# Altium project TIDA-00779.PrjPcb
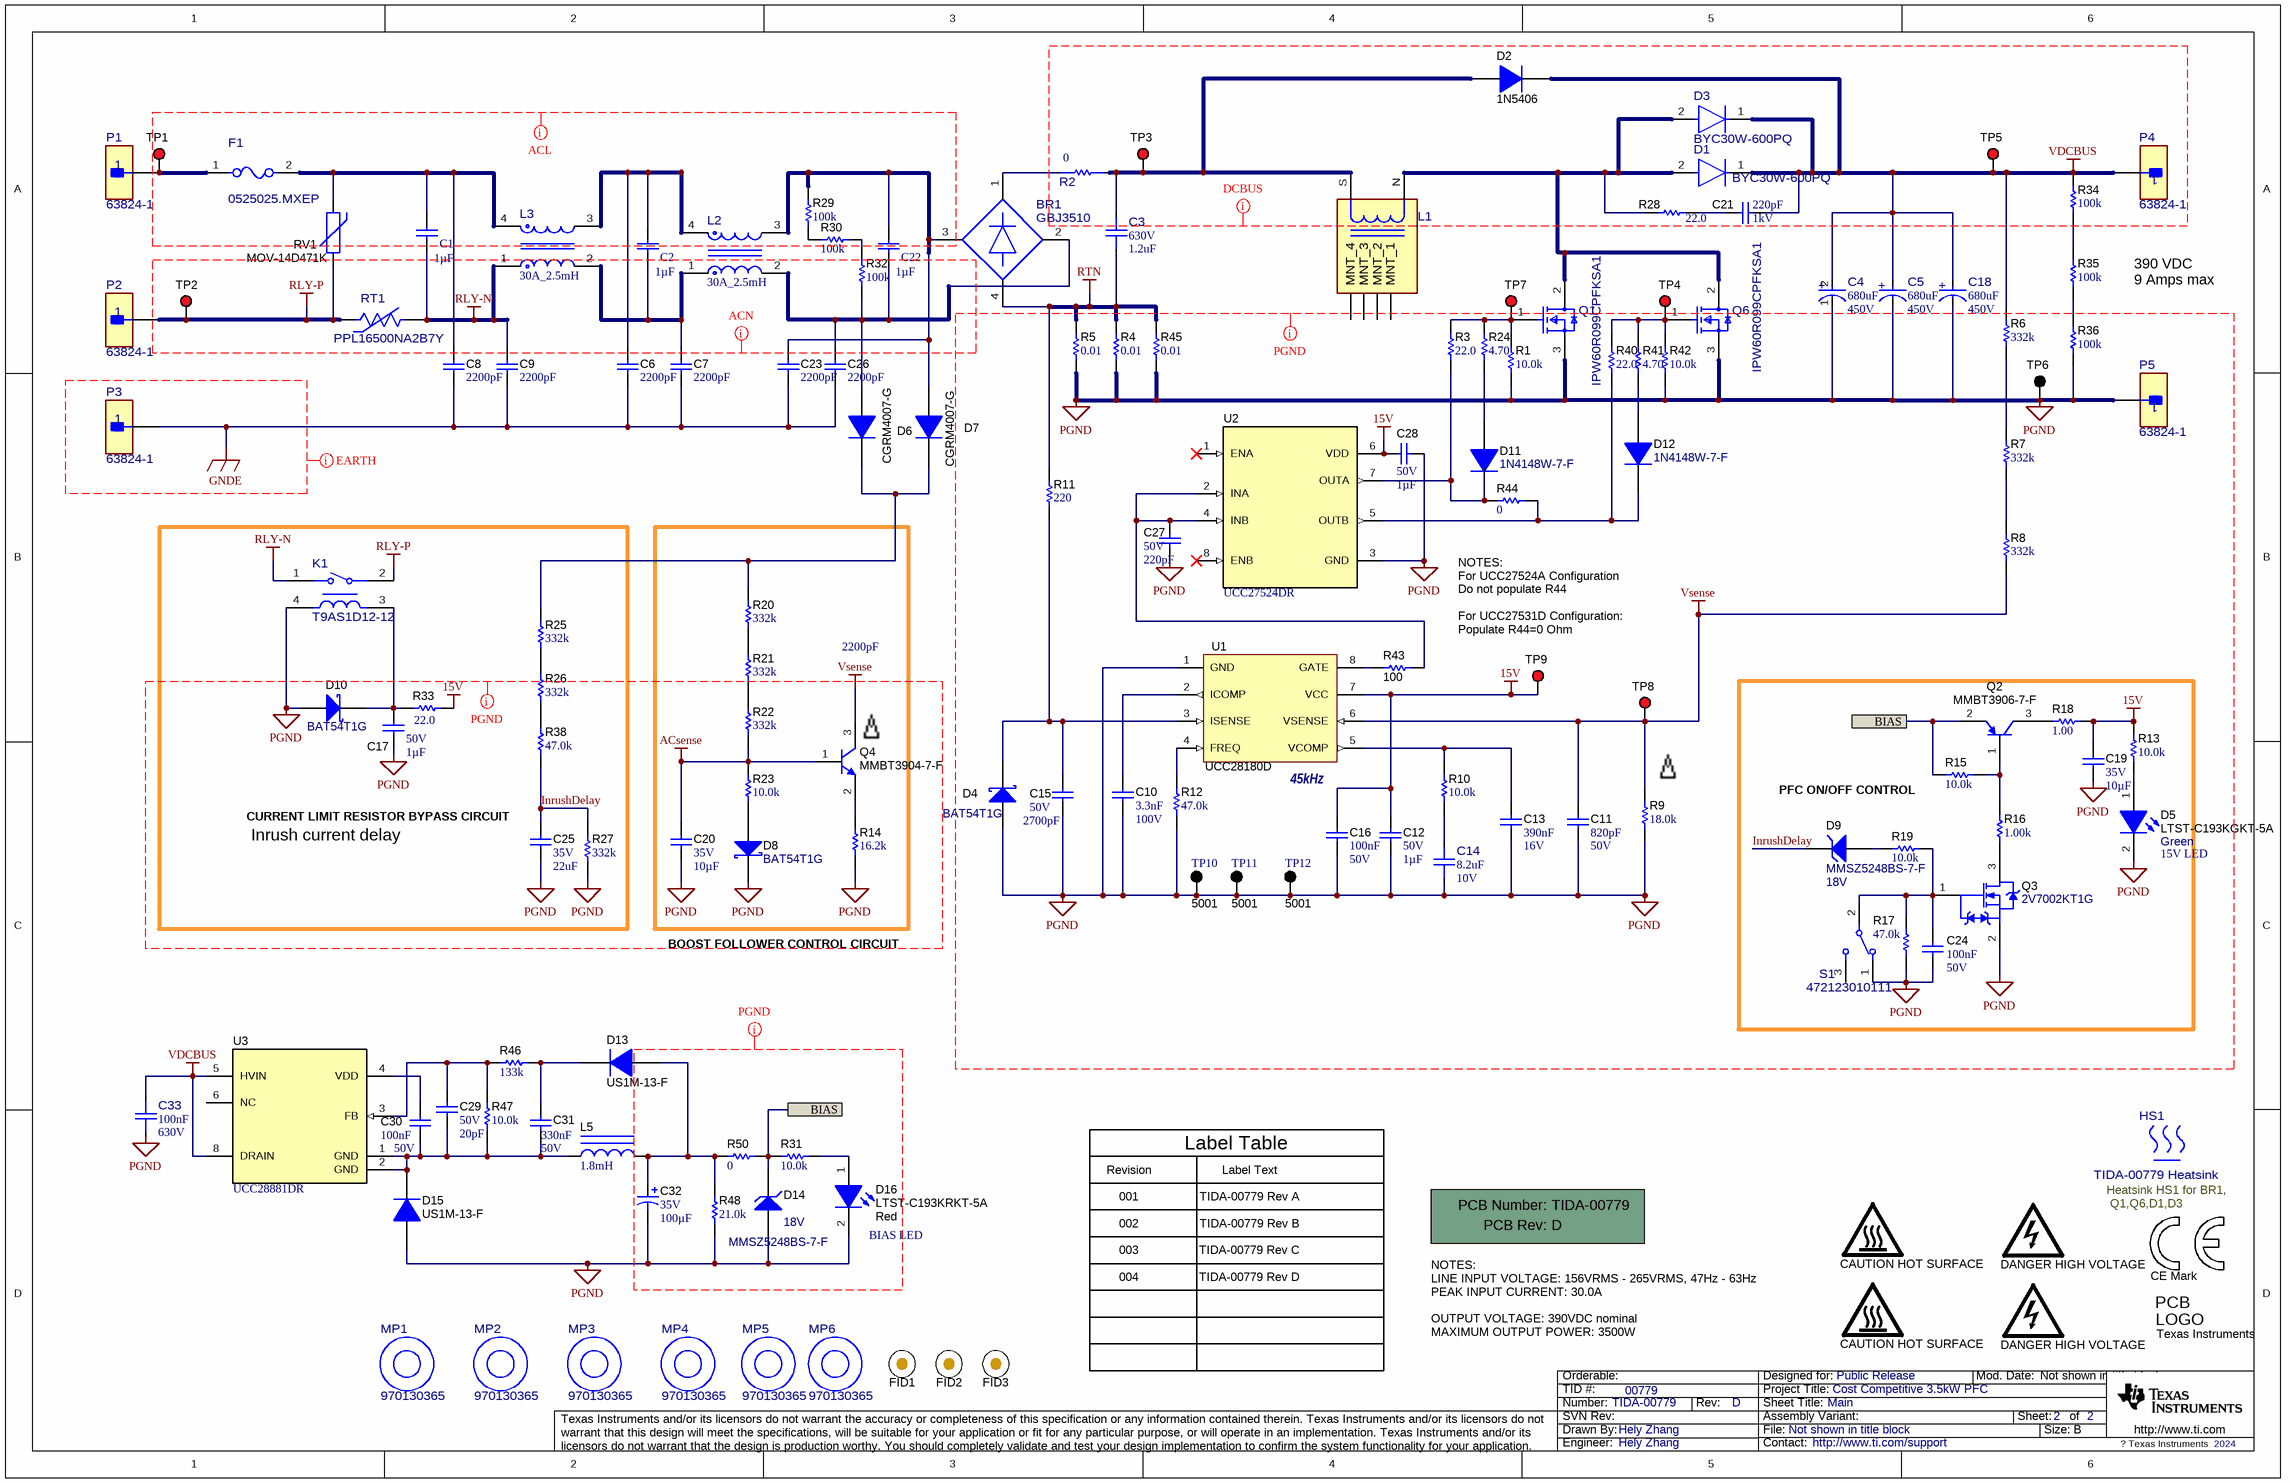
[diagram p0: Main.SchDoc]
CopyrightYear: 2024; PCB_Layout: Hely Zhang; PCB_Rev: D; PRJ_Customer: Public Release; PRJ_Engineer: Hely Zhang; PRJ_Number: TIDA-00779; PRJ_Title: Cost Competitive 3.5kW PFC; SCH_Rev: D; TechSupport: http://www.ti.com/support; TID: 00779
2 sheets, 148 parts. Net scope: flat (ports and power ports of the same name join across sheets).
Board file: TIDA-00779.PcbDoc
Sheets:
  BlockDiagram.SchDoc
  Main.SchDoc

## Sheet BlockDiagram.SchDoc: BlockDiagram
size A4; Date: Not shown in title block; ApprovedBy: Not shown in title block; CheckedBy: Not shown in title block; Author: Not shown in title block; CompanyName: Not shown in title block; DrawnBy: Hely Zhang; Engineer: Not shown in title block; Organization: Not shown in title block; Address1: Not shown in title block; Address2: Not shown in title block; Address3: Not shown in title block; Address4: Not shown in title block; DocumentNumber: 1; Revision: Use project parameter SCH_Rev; SheetNumber: 1; SheetTotal: 2; PageSetup: Record=PageOptions¦CenterHorizontal=True¦CenterVertical=True¦PrintScale=0.93¦XCorrection=1.00¦YCorrection=1.00¦PrintKind=0¦BorderSize=5000000¦LeftOffset=0¦BottomOffset=0¦Orientation=2¦PaperLength=1000¦PaperWidth=1000¦Scale=100¦PaperSource=15¦PrintQuality=600¦MediaType=1¦DitherType=10¦PaperKind=Letter¦PrintScaleMode=1

## Sheet Main.SchDoc: Main
size 431 x 279 mm; Date: Not shown in title block; ApprovedBy: Hely Zhang; CheckedBy: Hely Zhang; Author: Hely Zhang; CompanyName: TI; DrawnBy: Hely Zhang; Engineer: Not shown in title block; Organization: Not shown in title block; Address1: Not shown in title block; Address2: Not shown in title block; Address3: Not shown in title block; Address4: Not shown in title block; DocumentNumber: 1; Revision: Use project parameter SCH_Rev; SheetNumber: 2; SheetTotal: 2; PageSetup: Record=PageOptions¦CenterHorizontal=True¦CenterVertical=True¦PrintScale=0.62¦XCorrection=1.00¦YCorrection=1.00¦PrintKind=0¦BorderSize=5000000¦LeftOffset=0¦BottomOffset=0¦Orientation=2¦PaperLength=1000¦PaperWidth=1000¦Scale=100¦PaperSource=15¦PrintQuality=600¦MediaType=1¦DitherType=10¦PaperKind=Letter¦PrintScaleMode=1

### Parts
!PCB1  Printed Circuit Board  (value not drawn)  (mechanical)
BR1  GBJ3510  [FP-GBJ3510_HOR_GBJ3510_HOR-MFG]
C1  Cap_F: 1µF  [WCAP-FTXX_L26W11H20_CS]  (hidden comment: 890334026027CS)
C2  Cap_F: 1µF  [WCAP-FTXX_L26W11H20_CS]  (hidden comment: 890334026027CS)
C3  VDC_V: 630V  ValueDisplayed: 1.2uF  [FP-890334027012CS_RADIAL-MFG]  (hidden comment: 890334027012CS)
C4  ValueDisplayed: 680uF  VDC_V: 450V  [FP-861141486026_RADIAL-MFG]  (hidden comment: 861141486026)
C5  ValueDisplayed: 680uF  VDC_V: 450V  [FP-861141486026_RADIAL-MFG]  (hidden comment: 861141486026)
C6  ValueDisplayed: 2200pF  [KY_800x500x1100]  (hidden comment: DE2E3KY222MA2BM01F)
C7  ValueDisplayed: 2200pF  [KY_800x500x1100]  (hidden comment: DE2E3KY222MA2BM01F)
C8  ValueDisplayed: 2200pF  [KY_800x500x1100]  (hidden comment: DE2E3KY222MA2BM01F)
C9  ValueDisplayed: 2200pF  [KY_800x500x1100]  (hidden comment: DE2E3KY222MA2BM01F)
C10  Cap_F: 3.3nF  VDC_V: 100V  [0603]  (hidden comment: GRM188R72A332KA01D)
C11  Cap_F: 820pF  VDC_V: 50V  [0603]  (hidden comment: GRM188R71H821KA01D)
C12  VDC_V: 50V  ValueDisplayed: 1µF  [0603]  (hidden comment: GRT188R61H105ME13D)
C13  Cap_F: 390nF  VDC_V: 16V  [0603]  (hidden comment: GRM188R71C394KA88D)
C14  ValueDisplayed: 8.2uF  VDC_V: 10V  [FP-C1206C825M8RAC7800_1206-MFG]  (hidden comment: C1206C825M8RAC7800)
C15  VDC_V: 50V  ValueDisplayed: 2700pF  [0603]  (hidden comment: GRM1885C1H272JA01D)
C16  Cap_F: 100nF  VDC_V: 50V  [0603]  (hidden comment: GCM188R71H104KA57D)
C17  VDC_V: 50V  ValueDisplayed: 1µF  [0603]  (hidden comment: GRT188R61H105ME13D)
C18  ValueDisplayed: 680uF  VDC_V: 450V  [FP-861141486026_RADIAL-MFG]  (hidden comment: 861141486026)
C19  VDC_V: 35V  ValueDisplayed: 10µF  [1206]  (hidden comment: GRM319R6YA106KA12D)
C20  VDC_V: 35V  ValueDisplayed: 10µF  [1206]  (hidden comment: GRM319R6YA106KA12D)
C21  VDC_V: 1kV  ValueDisplayed: 220pF  [1206]  (hidden comment: GRM31A7U3A221JW31D)
C22  Cap_F: 1µF  [WCAP-FTXX_L26W11H20_CS]  (hidden comment: 890334026027CS)
C23  ValueDisplayed: 2200pF  [KY_800x500x1100]  (hidden comment: DE2E3KY222MA2BM01F)
C24  Cap_F: 100nF  VDC_V: 50V  [0603]  (hidden comment: GCM188R71H104KA57D)
C25  VDC_V: 35V  ValueDisplayed: 22uF  [1206_180]  (hidden comment: C3216X5R1V226M160AC)
C26  ValueDisplayed: 2200pF  [KY_800x500x1100]  (hidden comment: DE2E3KY222MA2BM01F)
C27  VDC_V: 50V  ValueDisplayed: 220pF  [0603]  (hidden comment: GRM1885C1H221JA01D)
C28  VDC_V: 50V  ValueDisplayed: 1µF  [0603]  (hidden comment: GRT188R61H105ME13D)
C29  VDC_V: 50V  ValueDisplayed: 20pF  [0603]  (hidden comment: GRM1885C1H200JA01D)
C30  Cap_F: 100nF  VDC_V: 50V  [0603]  (hidden comment: GCM188R71H104KA57D)
C31  Cap_F: 330nF  VDC_V: 50V  [0805_HV]  (hidden comment: GRM219R71H334KA88D)
C32  VDC_V: 35V  ValueDisplayed: 100µF  [Rubycon_630x1100]  (hidden comment: 35ZLJ100M6.3X11)
C33  ValueDisplayed: 100nF  VDC_V: 630V  [FP-885342211006_1812-MFG]  (hidden comment: 885342211006)
D1  BYC30W-600PQ  [FP-BYC30W-600PQ_HOR_TO-247-2-MFG]
D2  1N5406  [DO-201AD]
D3  BYC30W-600PQ  [FP-BYC30W-600PQ_HOR_TO-247-2-MFG]
D4  BAT54T1G  [SOD-123]
D5  LTST-C193KGKT-5A  value Green  [LTST-C193_Green]
D6  CGRM4007-G  [MINI-SMA]
D7  CGRM4007-G  [MINI-SMA]
D8  BAT54T1G  [SOD-123]
D9  MMSZ5248BS-7-F  value 18V  [SOD-323]
D10  BAT54T1G  [SOD-123]
D11  1N4148W-7-F  [SOD-123]
D12  1N4148W-7-F  [SOD-123]
D13  US1M-13-F  [SMA]
D14  MMSZ5248BS-7-F  value 18V  [SOD-323]
D15  US1M-13-F  [SMA]
D16  LTST-C193KRKT-5A  value Red  [LTST-C193_Red]
F1  0525025.MXEP  [FP-0525025.MXEP_AXIAL-MFG]
FID1  Fiducial  [Fiducial10-20]  (value not drawn)
FID2  Fiducial  [Fiducial10-20]  (value not drawn)
FID3  Fiducial  [Fiducial10-20]  (value not drawn)
HS1  TIDA-00779 Heatsink  [0-MFG]
K1  T9AS1D12-12  [FP-T9AS1D12-12_PTH_RELAY_27MM43_32MM51-MFG]
L1  30A_170uH  [FP-30A_170uH_PTH_IND_60MM0_51MM0-MFG]  (value not drawn)
L2  30A_2.5mH  [FP-30A_2.5mH_PTH_CMC_56MM0_42MM0-MFG]
L3  30A_2.5mH  [FP-30A_2.5mH_PTH_CMC_56MM0_42MM0-MFG]
L5  ValueDisplayed: 1.8mH  [WE-TI_8095]  (hidden comment: 768772182)
LOGO1  CAUTION HOT SURFACE  [IEC_HotSurface_Small]  (no BOM)
LOGO3  CAUTION HOT SURFACE  [IEC_HotSurface_Small]  (no BOM)
LOGO4  DANGER HIGH VOLTAGE  [IEC_HighVoltage_Small]  (no BOM)
Logo5  CE Mark  [CE_Mark_5mm]  (no BOM)
Logo6  Texas Instruments  [TI_Stacked_Overlay_Small]  (no BOM)
MP1  970130365  [FP-970130365_SPCAER_M3-MFG]
MP2  970130365  [FP-970130365_SPCAER_M3-MFG]
MP3  970130365  [FP-970130365_SPCAER_M3-MFG]
MP4  970130365  [FP-970130365_SPCAER_M3-MFG]
MP5  970130365  [FP-970130365_SPCAER_M3-MFG]
MP6  970130365  [FP-970130365_SPCAER_M3-MFG]
P1  63824-1  [FP-63824-1_CONN_7MM92_3MM11-MFG]
P2  63824-1  [FP-63824-1_CONN_7MM92_3MM11-MFG]
P3  63824-1  [FP-63824-1_CONN_7MM92_3MM11-MFG]
P4  63824-1  [FP-63824-1_CONN_7MM92_3MM11-MFG]
P5  63824-1  [FP-63824-1_CONN_7MM92_3MM11-MFG]
Q1  IPW60R099CPFKSA1  [FP-IPW60R099CPFKSA1_HOR_TO247-MFG]
Q2  MMBT3906-7-F  [SOT-23]
Q3  2V7002KT1G  [SOT-23]
Q4  MMBT3904-7-F  [SOT-23]
Q6  IPW60R099CPFKSA1  [FP-IPW60R099CPFKSA1_HOR_TO247-MFG]
R1  ValueDisplayed: 10.0k  [0603]  (hidden comment: RC0603FR-0710KL)
R2  value 0  [FP-RC2512FK-070RL_2512-MFG]  (hidden comment: RC2512FK-070RL)
R3  ValueDisplayed: 22.0  [1206]  (hidden comment: RC1206FR-0722RL)
R4  ValueDisplayed: 0.01  [2512]  (hidden comment: ERJ-M1WSF10MU)
R5  ValueDisplayed: 0.01  [2512]  (hidden comment: ERJ-M1WSF10MU)
R6  ValueDisplayed: 332k  [1206]  (hidden comment: RC1206FR-07332KL)
R7  ValueDisplayed: 332k  [1206]  (hidden comment: RC1206FR-07332KL)
R8  ValueDisplayed: 332k  [1206]  (hidden comment: RC1206FR-07332KL)
R9  ValueDisplayed: 18.0k  [0603]  (hidden comment: RC0603FR-0718KL)
R10  ValueDisplayed: 10.0k  [0603]  (hidden comment: RC0603FR-0710KL)
R11  ValueDisplayed: 220  [0603]  (hidden comment: RC0603FR-07220RL)
R12  ValueDisplayed: 47.0k  [0603]  (hidden comment: RC0603FR-0747KL)
R13  ValueDisplayed: 10.0k  [0603]  (hidden comment: RC0603FR-0710KL)
R14  ValueDisplayed: 16.2k  [0603]  (hidden comment: RC0603FR-0716K2L)
R15  ValueDisplayed: 10.0k  [0603]  (hidden comment: RC0603FR-0710KL)
R16  ValueDisplayed: 1.00k  [0603]  (hidden comment: RC0603FR-071KL)
R17  ValueDisplayed: 47.0k  [0603]  (hidden comment: RC0603FR-0747KL)
R18  ValueDisplayed: 1.00  [1206]  (hidden comment: RC1206FR-071RL)
R19  ValueDisplayed: 10.0k  [0603]  (hidden comment: RC0603FR-0710KL)
R20  ValueDisplayed: 332k  [1206]  (hidden comment: RC1206FR-07332KL)
R21  ValueDisplayed: 332k  [1206]  (hidden comment: RC1206FR-07332KL)
R22  ValueDisplayed: 332k  [1206]  (hidden comment: RC1206FR-07332KL)
R23  ValueDisplayed: 10.0k  [0603]  (hidden comment: RC0603FR-0710KL)
R24  ValueDisplayed: 4.70  [1206]  (hidden comment: RC1206FR-074R7L)
R25  ValueDisplayed: 332k  [1206]  (hidden comment: RC1206FR-07332KL)
R26  ValueDisplayed: 332k  [1206]  (hidden comment: RC1206FR-07332KL)
R27  ValueDisplayed: 332k  [1206]  (hidden comment: RC1206FR-07332KL)
R28  ValueDisplayed: 22.0  [1206]  (hidden comment: RC1206FR-0722RL)
R29  ValueDisplayed: 100k  [1206]  (hidden comment: RC1206FR-07100KL)
R30  ValueDisplayed: 100k  [1206]  (hidden comment: RC1206FR-07100KL)
R31  ValueDisplayed: 10.0k  [0603]  (hidden comment: RC0603FR-0710KL)
R32  ValueDisplayed: 100k  [1206]  (hidden comment: RC1206FR-07100KL)
R33  ValueDisplayed: 22.0  [1206]  (hidden comment: RC1206FR-0722RL)
R34  ValueDisplayed: 100k  [1206]  (hidden comment: RC1206FR-07100KL)
R35  ValueDisplayed: 100k  [1206]  (hidden comment: RC1206FR-07100KL)
R36  ValueDisplayed: 100k  [1206]  (hidden comment: RC1206FR-07100KL)
R38  ValueDisplayed: 47.0k  [0603]  (hidden comment: RC0603FR-0747KL)
R40  ValueDisplayed: 22.0  [1206]  (hidden comment: RC1206FR-0722RL)
R41  ValueDisplayed: 4.70  [1206]  (hidden comment: RC1206FR-074R7L)
R42  ValueDisplayed: 10.0k  [0603]  (hidden comment: RC0603FR-0710KL)
R43  ValueDisplayed: 100  [0603]  (hidden comment: RT0603DRE07100RL)
R44  ValueDisplayed: 0  [0603]  (hidden comment: RC0603JR-070RL)
R45  ValueDisplayed: 0.01  [2512]  (hidden comment: ERJ-M1WSF10MU)
R46  ValueDisplayed: 133k  [0603]  (hidden comment: RC0603FR-07133KL)
R47  ValueDisplayed: 10.0k  [0603]  (hidden comment: RC0603FR-0710KL)
R48  ValueDisplayed: 21.0k  [0603]  (hidden comment: RC0603FR-0721KL)
R50  ValueDisplayed: 0  [0603]  (hidden comment: RC0603JR-070RL)
RT1  PPL16500NA2B7Y  [FP-PPL16500NA2B7Y_RADIAL-MFG]
RV1  MOV-14D471K  [Bourns_MOV-14D621K]
S1  472123010111  [FP-472123010111_PTH3-MFG]
TP1  5000  [Keystone5000]  (value not drawn)
TP2  5000  [Keystone5000]  (value not drawn)
TP3  5000  [Keystone5000]  (value not drawn)
TP4  5000  [Keystone5000]  (value not drawn)
TP5  5000  [Keystone5000]  (value not drawn)
TP6  5001  [Keystone5001]  (value not drawn)
TP7  5000  [Keystone5000]  (value not drawn)
TP8  5000  [Keystone5000]  (value not drawn)
TP9  5000  [Keystone5000]  (value not drawn)
TP10  5001  [Keystone5001]
TP11  5001  [Keystone5001]
TP12  5001  [Keystone5001]
U1  UCC28180D  [D0008A_N]
U2  UCC27524DR  [D0008A_N]
U3  UCC28881DR  [D0007A_N]
  DANGER HIGH VOLTAGE  [IEC_HighVoltage_Small]  (no BOM)

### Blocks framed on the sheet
Inrush current delay: C17 C25 D10 K1 R25-R27 R33 R38
2200pF: C20 D8 Q4 R14 R20-R23
15V LED: C19 C24 D5 D9 Q2 Q3 R13 R15-R19 S1

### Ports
BIAS

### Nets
15V: C12.1 C16.1 C19.1 C28.2 R13.1 R18.2 R33.1 TP9.1 U1.7(VCC) U2.6(VDD)
ACsense: C20.1 Q4.1(B) R22.1 R23.2
GNDE: C6.1 C7.1 C8.1 C9.1 C23.1 C26.1 P3.1
PGND: C4.1(CATHODE) C5.1(CATHODE) C10.2 C11.2 C12.2 C13.2 C14.1 C15.2 C16.2 C17.2 C18.1(CATHODE) C19.2 C20.2 C24.2 C25.2 C27.2 C28.1 C32.2(-) C33.1 D4.2(A) D5.2(K) D8.1(K) D10.2(A) D14.2(A) D15.2(A) D16.2(K) K1.4 P5.1 Q1.3(source) Q3.2(S) Q6.3(source) R1.1 R4.1 R5.1 R9.1 R12.1 R14.1 R17.1 R27.1 R36.1 R42.1 R45.1 R48.1 S1.1 TP6.1 TP10.1 TP11.1 TP12.1 U1.1(GND) U2.3(GND)
RLY-N: C1.1 C9.2 K1.1 L3.1 RT1.2
RLY-P: K1.2 P2.1 RT1.1 RV1.1 TP2.1
RTN: BR1.4(-) C3.1 R4.2 R5.2 R11.2 R45.2
VDCBUS: C4.2(ANODE) C5.2(ANODE) C18.2(ANODE) C21.1 C33.2 D1.1(K) D2.1(K) D3.1(K) P4.1 R6.2 R34.2 TP5.1 U3.5(HVIN) U3.8(DRAIN)
Vsense: C11.1 Q4.3(C) R8.1 R9.2 TP8.1 U1.6(VSENSE)
BIAS: D14.1(K) Q2.2(E) R15.1 R31.2 R50.2 ; port BIAS
InrushDelay: C25.1 D9.1(K) R27.2 R38.1
NetBR1_1: BR1.1(+) R2.1
NetBR1_2: BR1.2(1_~) C22.1 C26.2 D6.2(A) L2.2 R32.1
NetBR1_3: BR1.3(2_~) C22.2 C23.2 D7.2(A) L2.3 R29.2
NetC1_2: C1.2 C8.2 F1.2 L3.4 RV1.2
NetC2_1: C2.1 C7.2 L2.1 L3.2
NetC2_2: C2.2 C6.2 L2.4 L3.3
NetC3_2: C3.2 D2.2(A) L1.S R2.2 TP3.1
NetC10_1: C10.1 U1.2(ICOMP)
NetC13_1: C13.1 R10.2 U1.5(VCOMP)
NetC14_2: C14.2 R10.1
NetC15_1: C15.1 D4.1(K) R11.1 U1.3(ISENSE)
NetC17_1: C17.1 D10.1(K) K1.3 R33.2
NetC21_2: C21.2 R28.1
NetC24_1: C24.1 Q3.1(G) R17.2 R19.1 S1.2
NetC27_1: C27.1 R43.2 U2.2(INA) U2.4(INB)
NetC29_1: C29.1 R46.1 R47.2 U3.3(FB)
NetC29_2: C29.2 C30.2 C31.2 D15.1(K) L5.1 R47.1 U3.1(GND) U3.2(GND)
NetC30_1: C30.1 U3.4(VDD)
NetC31_1: C31.1 D13.1(K) R46.2
NetC32_1: C32.1(+) D13.2(A) L5.2 R48.2 R50.1
NetD1_2: D1.2(A) D3.2(A) L1.N Q1.2(drain) Q6.2(drain) R28.2
NetD5_1: D5.1(A) R13.2
NetD6_1: D6.1(K) D7.1(K) R20.2 R25.2
NetD8_2: D8.2(A) R23.1
NetD9_2: D9.2(A) R19.2
NetD11_1: D11.1(K) R3.1 R44.1 U2.7(OUTA)
NetD11_2: D11.2(A) R24.1
NetD12_1: D12.1(K) R40.1 R44.2 U2.5(OUTB)
NetD12_2: D12.2(A) R41.1
NetD16_1: D16.1(A) R31.1
NetF1_1: F1.1 P1.1 TP1.1
NetQ1_1: Q1.1(gate) R1.2 R3.2 R24.2 TP7.1
NetQ2_1: Q2.1(B) R15.2 R16.1
NetQ2_3: Q2.3(C) R18.1
NetQ3_3: Q3.3(D) R16.2
NetQ4_2: Q4.2(E) R14.2
NetQ6_1: Q6.1(gate) R40.2 R41.2 R42.2 TP4.1
NetR6_1: R6.1 R7.2
NetR7_1: R7.1 R8.2
NetR12_2: R12.2 U1.4(FREQ)
NetR20_1: R20.1 R21.2
NetR21_1: R21.1 R22.2
NetR25_1: R25.1 R26.2
NetR26_1: R26.1 R38.2
NetR29_1: R29.1 R30.2
NetR30_1: R30.1 R32.2
NetR34_1: R34.1 R35.2
NetR35_1: R35.1 R36.2
NetR43_1: R43.1 U1.8(GATE)

Not connected (* = marked no-connect by the designer): L1 1(MNT_1) 2(MNT_2) 3(MNT_3) 4(MNT_4); S1 3; U2 1(ENA)* 8(ENB)*; U3 6(NC)

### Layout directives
net class PGND: 15V, (no net found under the mark), ACsense, InrushDelay, PGND, Vsense
net class ACL: (no net found under the mark)
net class ACN: RLY-N, RLY-P
net class DCBUS: VDCBUS
net class EARTH: GNDE

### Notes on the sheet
- 390 VDC
  9 Amps max
- NOTES:
  For UCC27524A Configuration
  Do not populate R44
  For UCC27531D Configuration:
  Populate R44=0 Ohm
- CURRENT LIMIT RESISTOR BYPASS CIRCUIT
- (near U1) 45kHz
- (near R15) PFC ON/OFF CONTROL
- BOOST FOLLOWER CONTROL CIRCUIT
- Revision
- Label Table
- Label Text
- (near D16) BIAS LED
- 001
- 002
- TIDA-00779 Rev A
- TIDA-00779 Rev B
- Q1,Q6,D1,D3
- Heatsink HS1 for BR1,
- 003
- 004
- TIDA-00779 Rev C
- TIDA-00779 Rev D
- (near !PCB1) NOTES:
  LINE INPUT VOLTAGE: 156VRMS - 265VRMS, 47Hz - 63Hz
  PEAK INPUT CURRENT: 30.0A
  OUTPUT VOLTAGE: 390VDC nominal
  MAXIMUM OUTPUT POWER: 3500W

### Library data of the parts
!PCB1 = CMP-0003618-2: Manufacturer: Any; PartNumber: TIDA-00779
BR1 = CMP-0121868-2: Bridge Rectifier Single Phase Standard 1 kV Through Hole GBJ; Manufacturer: SMC Diode Solutions; PartNumber: GBJ3510_HOR; AEC Qualified: No; SizeZ_mm: 4.8mm; TJmax_C: 150°C; Vf_V: 1kV; Cap_F: 75pF; Forward Current: 35A; Max Surge Forward Current: 320A; Peak Reverse Current: 5uA; AEC Category: Q101; CompType: Diode
C1 C2 C22 = CMP-0112728-1: WCAP-FTXX Film Capacitor, THT, L26 x W11 x H20mm, 1µF, 310V; Manufacturer: Wurth Elektronik; Capacitance Tolerance: +/-10%; Dissipation Factor @10kHz: 0.7%; Dissipation Factor @1kHz: 0.1%; Insulation Resistance: 10000Ohm x F; Pitch: 22.5mm; Rate of Voltage Rise: 170V/us; Technical Reference: MXXP225105K310ACPP36004
C3 = CMP-0090546-1: 1.2µF Film Capacitor 310V  Polypropylene (PP), Metallized Radial; Manufacturer: Wurth Electronics; AEC Qualified: No; Tolerance_%: 10%; SizeZ_mm: 22.5mm
C4 C5 C18 = CMP-0035874-1: 680 µF 450 V Aluminum Electrolytic Capacitors Radial, Can - Snap-In 3000 Hrs @ 105°C; Manufacturer: Wurth Eectronics; AEC Qualified: No; Cap_F: 680µF; IRMS_A: 2.2A; SizeZ_mm: 59mm; Tolerance_%: 20%; Leakage Current: 1659.52uA; Life: 3000Hours; Value: 680µF
C6-C9 C23 C26 = CMP-0067532-1: CAP, CERM, 2200 pF, X1 250 VAC/Y2 250 VAC, +/- 20%, E, 8x5mm; Manufacturer: MuRata; TaMin_C: -40°C; AC_Safety: X1Y2; Polarized: N; SizeAreaWB_mm2: 70.0; Value1: Unknown; U/M: EA; Value: 2200pF; TaMax_C: 125°C; VAC_X: 250; SizeZ_mm: 11.0; SizeX_mm: 8.0; SizeY_mm: 5.0; Cap_Case: 8x5x11mm; Value2: V; SizeArea_mm2: 40.0; Cap_F: 2.2nF; AEC Category: Q200
C10 = CMP-0007479-4: CAP, CERM, 3300 pF, 100 V, +/- 10%, X7R, 0603; Manufacturer: MuRata; TaMin_C: -55°C; Polarized: N; SizeAreaWB_mm2: 4.68; Value1: Unknown; U/M: EA; Value: 3300pF; TaMax_C: 125°C; SizeZ_mm: 1; SizeX_mm: 1.6; SizeY_mm: 0.8; SizeArea_mm2: 1.28; AEC Category: Q200
C11 = CMP-0007464-4: CAP, CERM, 820 pF, 50 V, +/- 10%, X7R, 0603; Manufacturer: MuRata; TaMin_C: -55°C; Polarized: N; SizeAreaWB_mm2: 4.68; Value1: Unknown; U/M: EA; Value: 820pF; TaMax_C: 125°C; SizeZ_mm: 1; SizeX_mm: 1.6; SizeY_mm: 0.8; SizeArea_mm2: 1.28; AEC Category: Q200
C12 C17 C28 = CMP-0081784-1: CAP, CERM, 1 µF, 50 V,+/- 20%, X5R, AEC-Q200 Grade 3, 0603; Manufacturer: MuRata; TaMin_C: -55°C; Polarized: N; SizeAreaWB_mm2: 4.68; U/M: EA; Value: 1uF; TaMax_C: 85°C; SizeZ_mm: 1; SizeX_mm: 1.6; SizeY_mm: 0.8; SizeArea_mm2: 1.28; AEC Qualified: Y; AEC Grade: 3; AEC Category: Q200
C13 = CMP-0007395-4: CAP, CERM, 0.39 uF, 16 V, +/- 10%, X7R, 0603; Manufacturer: MuRata; TaMin_C: -55°C; Polarized: N; SizeAreaWB_mm2: 4.68; Value1: Unknown; U/M: EA; Value: 0.39uF; TaMax_C: 125°C; SizeZ_mm: 1; SizeX_mm: 1.6; SizeY_mm: 0.8; SizeArea_mm2: 1.28; AEC Category: Q200
C14 = CMP-0122046-1: Cap Ceramic 8.2uF 10V X7R 20% SMD 1206 125°C Plastic T/R; Manufacturer: KEMET; AEC Qualified: No; Cap_F: 8.2µF; SizeZ_mm: 1.8mm; TempCo: 15%; Value: 8.2µF
C15 = CMP-0007204-4: CAP, CERM, 2700 pF, 50 V, +/- 5%, C0G/NP0, 0603; Manufacturer: MuRata; TaMin_C: -55°C; Polarized: N; SizeAreaWB_mm2: 4.68; Value1: Unknown; U/M: EA; Value: 2700pF; TaMax_C: 125°C; SizeZ_mm: 1; SizeX_mm: 1.6; SizeY_mm: 0.8; SizeArea_mm2: 1.28; Cap_F: 2.7nF; AEC Category: Q200
C16 C24 C30 = CMP-0007144-4: CAP, CERM, 0.1 uF, 50 V, +/- 10%, X7R, 0603; Manufacturer: MuRata; TaMin_C: -55°C; ESR_ohm: 20m; Polarized: N; SizeAreaWB_mm2: 4.68; Value1: 0.02 ohm; U/M: EA; Value: 0.1uF; TaMax_C: 125°C; SizeZ_mm: 1; SizeX_mm: 1.6; SizeY_mm: 0.8; SizeArea_mm2: 1.28; IRMS_A: 1.84A; AEC Category: Q200
C19 C20 = CMP-0081637-1: CAP, CERM, 10 µF, 35 V,+/- 10%, X5R, 1206; Manufacturer: MuRata; TaMin_C: -55°C; ESR_ohm: 1m; Polarized: N; SizeAreaWB_mm2: 10.92; Value1: 0.001 ohm; U/M: EA; Value: 10uF; TaMax_C: 85°C; SizeZ_mm: 1.35; SizeX_mm: 3.2; SizeY_mm: 1.6; SizeArea_mm2: 5.12; IRMS_A: 6A; AEC Category: Q200
C21 = CMP-0008899-2: CAP, CERM, 220 pF, 1000 V, +/- 5%, U2J, 1206; Manufacturer: MuRata; TaMin_C: -55°C; Polarized: N; SizeAreaWB_mm2: 10.92; Value1: Unknown; U/M: EA; Value: 220pF; TaMax_C: 125°C; SizeZ_mm: 1.35; SizeX_mm: 3.2; SizeY_mm: 1.6; Value2: 1000V; SizeArea_mm2: 5.12; AEC Category: Q200
C25 = CMP-0008667-2: CAP, CERM, 22 uF, 35 V, +/- 20%, X5R, 1206; Manufacturer: TDK; TaMin_C: -55°C; ESR_ohm: 2.398m; Polarized: N; SizeAreaWB_mm2: 10.92; Value1: 0.002398 ohm; U/M: EA; Value: 22uF; TaMax_C: 85°C; SizeZ_mm: 1.8; SizeX_mm: 3.2; SizeY_mm: 1.6; SizeArea_mm2: 5.12; Cap_F: 22µF; IRMS_A: 4.6851A; AEC Category: Q200
C27 = CMP-0007197-4: CAP, CERM, 220 pF, 50 V, +/- 5%, C0G/NP0, 0603; Manufacturer: MuRata; TaMin_C: -55°C; Polarized: N; SizeAreaWB_mm2: 4.68; Value1: Unknown; U/M: EA; Value: 220pF; TaMax_C: 125°C; SizeZ_mm: 1; SizeX_mm: 1.6; SizeY_mm: 0.8; SizeArea_mm2: 1.28; AEC Category: Q200
C29 = CMP-0007193-4: CAP, CERM, 20 pF, 50 V, +/- 5%, C0G/NP0, 0603; Manufacturer: MuRata; TaMin_C: -55°C; Polarized: N; SizeAreaWB_mm2: 4.68; Value1: Unknown; U/M: EA; Value: 20pF; TaMax_C: 125°C; SizeZ_mm: 1; SizeX_mm: 1.6; SizeY_mm: 0.8; SizeArea_mm2: 1.28; AEC Category: Q200
C31 = CMP-0008227-2: CAP, CERM, 0.33 uF, 50 V, +/- 10%, X7R, 0805; Manufacturer: MuRata; TaMin_C: -55°C; Polarized: N; SizeAreaWB_mm2: 6.75; Value1: Unknown; U/M: EA; Value: 0.33uF; TaMax_C: 125°C; SizeZ_mm: 1.45; SizeX_mm: 2; SizeY_mm: 1.25; Cap_Case: 0805; SizeArea_mm2: 2.5; AEC Category: Q200
C32 = CMP-0080807-1: CAP, AL, 100 µF, 35 V, +/- 20%, TH; Manufacturer: Rubycon; IRMS_A: 700mA; SizeAreaWB_mm2: 68.89; SizeArea_mm2: 39.69; AEC Qualified: N; AEC Category: Q200; Value: 100uF; TaMax_C: 105°C; SizeZ_mm: 12.5; Polarized: Y; TaMin_C: -40°C; SizeY_mm: 6.3; U/M: EA; CompType: Capacitor; Cap_Case: 6.3x11
C33 = CMP-0120776-1: 0.1μF ±10% 630V Ceramic Capacitor X7R 1812 (4532 Metric); Manufacturer: Wurth Electronics; AEC Qualified: No; SizeZ_mm: 2.2mm; TempCo: 15%; Value: 100nF
D1 D3 = CMP-0121865-2: Diode 600 V 30A Through Hole TO-247-2; Manufacturer: WeEn Semiconductors; PartNumber: BYC30W-600PQ_HOR; AEC Qualified: No; SizeZ_mm: 5.2mm; TJmax_C: 175°C; Vf_V: 600V; AEC Grade: NA; Max Surge Forward Current: 270A; Peak Reverse Current: 10uA; Standoff Height: 4.25mm; AEC Category: Q101
D2 = 1N5406: Diode, Switching-Bridge, 600 V, 3 A, TH; Manufacturer: Vishay-Semiconductor; U/M: EA; Vf_V: 1.2; Value: 600V; Value1: 3A; Value2: 1.2V; Io_A: 3; Vr_V: 600; TJmax_C: 150
D4 D8 D10 = CMP-0028457-2: Diode, Schottky, 30 V, 0.2 A, SOD-123; Manufacturer: ON Semiconductor; SizeArea_mm2: 6.545; Io_A: 200mA; SizeX_mm: 3.85; Value1: 0.2A; SizeY_mm: 1.7; AEC Category: Q101; Vf_V: 800mV; TJmax_C: 125°C; Green_Lifecycle: Not Set; RJC_CperW: 174; Value: 30V; Value2: 0.8V; SizeAreaWB_mm2: 13.095; Green_REACh: Incomplete; SizeZ_mm: 1.35
D5 = CMP-0079921-3: LED, Green, SMD; Manufacturer: Lite-On; Tjmax_C: 85°C; Value2: 2V; SizeY_mm: 0.8; Io_A: 5mA; SizeAreaWB_mm2: 4.68; Type: AlInGaP; SizeX_mm: 1.6; SizeZ_mm: 0.45; SizeArea_mm2: 1.28; Value1: W
D6 D7 = CGRM4007-G: Diode, P-N, 1000 V, 1 A, 3.9x1.7x1.8mm; Manufacturer: Comchip Technology; U/M: EA; Vf_V: 1.1; Value: 1000V; Value1: 1A; Value2: 1.1V; Io_A: 1; Vr_V: 1000; TJmax_C: 150
D9 D14 = CMP-0005835-4: Diode, Zener, 18 V, 200 mW, SOD-323; Manufacturer: Diodes Inc.; Value1: 0.2W; SizeArea_mm2: 3.645; AEC Category: Q101; Power_W: 200mW; SizeAreaWB_mm2: 8.695; SizeY_mm: 1.35; RJA_CperW: 350; SizeZ_mm: 1; SizeX_mm: 2.7
D11 D12 = CMP-0029001-1: Diode, Ultrafast, 100 V, 0.15 A, SOD-123; Manufacturer: Diodes Inc.; Io_A: 150mA; Green_Lifecycle: Active; SizeAreaWB_mm2: 13.095; Vr_V: 100V; Green_REACh: Passed; Value1: 0.15A; TJmax_C: 150°C; U/M: EA; Value: 100V; SizeZ_mm: 1.35; SizeX_mm: 3.85; SizeY_mm: 1.7; Vf_V: 1.25V; SizeArea_mm2: 6.545; AEC Category: Q101
D13 D15 = CMP-0076882-1: Diode, Ultrafast, 1000 V, 1 A, SMA; Manufacturer: Diodes Inc.; SizeAreaWB_mm2: 37.3428; Vr_V: 1kV; SizeArea_mm2: 16.3228; TJmax_C: 150°C; AEC Category: Q101; Value: 1000V; SizeZ_mm: 2.87; Green_REACh: Incomplete; Io_A: 1A; Vf_V: 1.7V; SizeY_mm: 2.92; Green_Lifecycle: Not Set; U/M: EA; SizeX_mm: 5.59; RJC_CperW: 30.0
D16 = CMP-0079922-3: LED, Red, SMD; Manufacturer: Lite-On; SizeX_mm: 1.6; Value2: 2V; SizeY_mm: 0.8; Green_REACh: Incomplete; SizeAreaWB_mm2: 4.68; Green_Lifecycle: Not Set; Value1: W; Io_A: 5mA; Type: AlInGaP; SizeZ_mm: 0.45; Tjmax_C: 85°C; SizeArea_mm2: 1.28
F1 = CMP-0090478-2: Manufacturer: Littelfuse; SizeZ_mm: 7.285mm; Fuse Interrupt Dc Current: 10000A; AEC Qualified: Yes; Res_ohm: 0.0038Ω; Fuse I2T: 320A2Sec; Fuse Current: 25A; AEC Grade: Grade 1; Interrupt_DC: 10kA; VDC_V: 450V
FID1-FID3 = Fiducial: Fiducial mark.  There is nothing to buy or mount.; SymbolCreator: codlsc
HS1 = CMP-0122056-1: Manufacturer: Texas Instruments; AEC Qualified: No; SizeZ_mm: 22mm
K1 = CMP-0121970-1: Electromechanical Relay 12VDC 144Ohm 30A SPST-NO (32.51x27.43x20.4)mm THT Industrial Relay; Manufacturer: TE; Coil Power_W: 1W; Coil Type: Non-Latching; Coil Voltage_VDC: 12V; SizeZ_mm: 20.4mm; AEC Qualified: No; Coil Resistance: 144Ω; Standoff Height: 0.33mm; TaMax_C: +85°C; TaMin_C: -55°C
L1 = CMP-0121837-1: PFC Inductor; Manufacturer: Qingdao Yunlu; AEC Qualified: No; DCR_ohm: 50m; Ind_H: 170µH; Irms: 30A; SizeZ_mm: 65mm; Value: 170uH; Test Frequency: 50kHz
L2 L3 = CMP-0121838-1: Common mode inductor; Manufacturer: Qingdao Yunlu; DCR_ohm: 2.5m; Ind_H: 2.5mH; SizeZ_mm: 52mm; AEC Qualified: No; Imax_A: 30A; Test Frequency: 100kHz
L5 = CMP-0064862-2: Inductor, Shielded Drum Core, Metal Composite, 1.8 mH, 0.35 A, 2.7 ohm, TH; Manufacturer: Wurth Elektronik; Isat: 0.38A @ 10% inductance drop; Irms: 0.35A @ 40C rise; Green_Lifecycle: Active; SizeAreaWB_mm2: 96.04; DCR_ohm: 2.7; Green_REACh: Passed; Value1: 2.7 ohm; Value: 1.8mH; Imax_A: 350mA; SizeZ_mm: 10; SizeX_mm: 7.8; Value2: 0.35A; SizeArea_mm2: 60.84; AEC Category: Q200
LOGO1 LOGO3 = CMP-0074837-1: IEC 61010-1 Hot Surface Warning; SymbolCreator: a0412235; Lib Reference: IEC_HotSurface
LOGO4  = CMP-0074835-1: IEC 61010-1 High Voltage Warning; SymbolCreator: a0412235; Lib Reference: IEC_HighVoltage
Logo5 = CMP-0074844-1: SymbolCreator: a0412235
Logo6 = CMP-0074838-1: Texas Instrument Corporate Signature; SymbolCreator: a0412235; Lib Reference: TI_Logo; Library Reference: Logo
MP1-MP6 = CMP-0087151-1: Manufacturer: Wurth Electronics
P1-P5 = CMP-0089624-1: Manufacturer: TE Connectivity; SizeZ_mm: 10.71mm; Conn Gender: Male; Conn Orientation: Straight; AEC Qualified: No; Import Ts: 1521847382; ContactFinish: Tin,Nickel; Current_A: 20A; Ciiva Ids: 766930
Q1 Q6 = CMP-0121869-2: Trans MOSFET N-CH 600V 31A 3-Pin(3+Tab) TO-247 Tube; Manufacturer: Infineon Technologies; PartNumber: IPW60R099CPFKSA1_HOR; AEC Qualified: No; QgTyp_nC: 60nC @ 10V; Rdson45_ohm: 90m; SizeZ_mm: 5.157mm; VdsMax_V: 1.2V; Vgs_V: 20V; ChMode: False; Input Capacitace At Vds: 2800pF @ 100V; Number Of Channels: 1; Power_W: 255W; Pulse Drain Current: 93A; Reverse Recovery Charge: 12000nC; Reverse Recovery Time: 450ns; Rthja Max: 62K/W; Threshold Vgs Max: 3.5V; Threshold Vgs Min: 2.5V; TJmax_C: +150°C; Turn Off Delay Time: 60ns; Turn On Delay Time: 10ns; Typ Forward Diode Voltage: 0.9V
Q2 = CMP-0000326-2: Transistor, PNP, 40 V, 0.2 A, SOT-23; Manufacturer: Diodes Inc.; TaMax_C: 150°C; Value2: 400; Value1: 0.2 A; Vcesat1_V: 250mV; SizeX_mm: 2.5; SizeY_mm: 3; TaMin_C: -55°C; IcRated_A: 200mA; CompType: BJT; SizeZ_mm: 1.1; Value: 40 V; SizeArea_mm2: 7.5; NPN: 0; Vceo_V: 40V; PNP: 1; AEC Category: Q101; SizeAreaWB_mm2: 14; U/M: EA
Q3 = CMP-0000777-1: MOSFET, N-CH, 60 V, 0.32 A, AEC-Q101, SOT-23; Alternate Manufacturer: None; Manufacturer: ON Semiconductor; SizeZ_mm: 1.1; ChType: N; Value2: 0.7 nC; Value1: 2; VdsMax_V: 60V; SizeX_mm: 2.5; SizeY_mm: 3; Vgs_V: 20V; AEC Qualified: Y; Value: 60V; SizeArea_mm2: 7.5; AEC Category: Q101; IdsMax_A: 320mA; SizeAreaWB_mm2: 14; U/M: EA; QgTyp_nC: 0.7
Q4 = CMP-0000387-2: Transistor, NPN, 40 V, 0.2 A, SOT-23; Manufacturer: Diodes Inc.; TaMax_C: 150°C; Value2: 400; Value1: 0.2 A; Vcesat1_V: 200mV; SizeX_mm: 2.5; SizeY_mm: 3; TaMin_C: -55°C; IcRated_A: 200mA; CompType: BJT; SizeZ_mm: 1.1; Value: 40 V; SizeArea_mm2: 7.5; NPN: 1; Vceo_V: 40V; PNP: 0; AEC Category: Q101; SizeAreaWB_mm2: 14; U/M: EA
R1 R10 R13 R15 R19 R23 R31 R42 R47 = CMP-0022746-5: RES, 10.0 k, 1%, 0.1 W, 0603; Manufacturer: Yageo; Power_W: 100mW; TempCo: 100 ppm/C; Value_Code: 10k0; Value: 10.0k; EIA_Code: E96; Res_ohm: 10k; SizeX_mm: 1.6; SizeY_mm: 0.8; SizeZ_mm: 1; Value2: 0.1W; SizeArea_mm2: 1.28; AEC Qualified: N; VDC_V: 75V; AEC Category: Q200; SizeAreaWB_mm2: 4.68
R2 = CMP-0096746-1: 0 Ohms Jumper 1W Chip Resistor 2512 (6432 Metric) Moisture Resistant Thick Film; Manufacturer: YAGEO; AEC Qualified: No; VDC_V: 200V; SizeZ_mm: 0.65mm; Max Current: 10A
R3 R28 R33 R40 = CMP-0018087-2: RES, 22.0, 1%, 0.25 W, 1206; Manufacturer: Yageo America; Power_W: 250mW; TempCo: 100 ppm/C; Value_Code: 22R0; U/M: EA; Value: 22.0; Res_ohm: 22; SizeX_mm: 3.2; SizeY_mm: 1.6; SizeZ_mm: 1.35; Value2: 0.25W; SizeArea_mm2: 5.12; VDC_V: 200V; AEC Category: Q200
R4 R5 R45 = CMP-0015807-2: RES, 0.01, 1%, 1 W, 2512; Manufacturer: Panasonic; Power_W: 1W; TempCo: 100 ppm/C; Value_Code: R010; U/M: EA; Value: 0.01; EIA_Code: E96; Res_ohm: 10m; SizeX_mm: 6.3; SizeY_mm: 3.2; SizeZ_mm: 0.71; SizeArea_mm2: 20.16; AEC Category: Q200
R6-R8 R20-R22 R25-R27 = CMP-0018207-2: RES, 332 k, 1%, 0.25 W, 1206; Manufacturer: Yageo America; Power_W: 250mW; TempCo: 100 ppm/C; U/M: EA; Value: 332k; EIA_Code: E96; SizeX_mm: 3.2; SizeY_mm: 1.6; SizeZ_mm: 1.35; Value2: 0.25W; SizeArea_mm2: 5.12; VDC_V: 200V; AEC Category: Q200
R9 = CMP-0022852-5: RES, 18.0 k, 1%, 0.1 W, 0603; Manufacturer: Yageo; Power_W: 100mW; TempCo: 100 ppm/C; Value_Code: 18k0; Value: 18.0k; Res_ohm: 18k; SizeX_mm: 1.6; SizeY_mm: 0.8; SizeZ_mm: 1; Value2: 0.1W; SizeArea_mm2: 1.28; AEC Qualified: N; VDC_V: 75V; AEC Category: Q200; SizeAreaWB_mm2: 4.68
R11 = CMP-0022918-5: RES, 220, 1%, 0.1 W, 0603; Manufacturer: Yageo; Power_W: 100mW; TempCo: 100 ppm/C; Value_Code: 220R; Value: 220; SizeX_mm: 1.6; SizeY_mm: 0.8; SizeZ_mm: 1; Value2: 0.1W; SizeArea_mm2: 1.28; AEC Qualified: N; VDC_V: 75V; AEC Category: Q200; SizeAreaWB_mm2: 4.68
R12 R17 R38 = CMP-0023133-5: RES, 47.0 k, 1%, 0.1 W, 0603; Manufacturer: Yageo; Power_W: 100mW; TempCo: 100 ppm/C; Value_Code: 47k0; Value: 47.0k; Res_ohm: 47k; SizeX_mm: 1.6; SizeY_mm: 0.8; SizeZ_mm: 1; Value2: 0.1W; SizeArea_mm2: 1.28; AEC Qualified: N; VDC_V: 75V; AEC Category: Q200; SizeAreaWB_mm2: 4.68
R14 = CMP-0022828-5: RES, 16.2 k, 1%, 0.1 W, 0603; Manufacturer: Yageo; Power_W: 100mW; TempCo: 100 ppm/C; Value_Code: 16k2; Value: 16.2k; EIA_Code: E96; SizeX_mm: 1.6; SizeY_mm: 0.8; SizeZ_mm: 1; Value2: 0.1W; SizeArea_mm2: 1.28; AEC Qualified: N; VDC_V: 75V; AEC Category: Q200; SizeAreaWB_mm2: 4.68
R16 = CMP-0022895-5: RES, 1.00 k, 1%, 0.1 W, 0603; Manufacturer: Yageo; Power_W: 100mW; TempCo: 100 ppm/C; Value_Code: 1k00; Value: 1.00k; EIA_Code: E96; Res_ohm: 1k; SizeX_mm: 1.6; SizeY_mm: 0.8; SizeZ_mm: 1; Value2: 0.1W; SizeArea_mm2: 1.28; AEC Qualified: N; VDC_V: 75V; AEC Category: Q200; SizeAreaWB_mm2: 4.68
R18 = CMP-0018059-2: RES, 1.00, 1%, 0.25 W, 1206; Manufacturer: Yageo America; Power_W: 250mW; TempCo: 200 ppm/C; Value_Code: 1R00; U/M: EA; Value: 1.00; EIA_Code: E96; Res_ohm: 1; SizeX_mm: 3.2; SizeY_mm: 1.6; SizeZ_mm: 1.35; Value2: 0.25W; SizeArea_mm2: 5.12; VDC_V: 200V; AEC Category: Q200
R24 R41 = CMP-0018350-2: RES, 4.70, 1%, 0.25 W, 1206; Manufacturer: Yageo America; Power_W: 250mW; TempCo: 200 ppm/C; Value_Code: 4R70; U/M: EA; Value: 4.70; Res_ohm: 4.7; SizeX_mm: 3.2; SizeY_mm: 1.6; SizeZ_mm: 1.35; Value2: 0.25W; SizeArea_mm2: 5.12; VDC_V: 200V; AEC Category: Q200
R29 R30 R32 R34-R36 = CMP-0017836-2: RES, 100 k, 1%, 0.25 W, 1206; Manufacturer: Yageo America; Power_W: 250mW; TempCo: 100 ppm/C; U/M: EA; Value: 100k; EIA_Code: E96; SizeX_mm: 3.2; SizeY_mm: 1.6; SizeZ_mm: 1.35; Value2: 0.25W; SizeArea_mm2: 5.12; VDC_V: 200V; AEC Category: Q200
R43 = RT0603DRE07100RL: RES, 100, 0.5%, 0.1 W, 0603; Manufacturer: Yageo America; CompType: Resistor; Value: 100; Value_Code: 100R; Tolerance_%: 0.5; Power_W: 0.1; Value2: 0.1W; VDC_V: 75; TempCo: 50 ppm/C; EIA_Code: E192; U/M: EA
R44 R50 = CMP-0025885-5: RES, 0, 5%, 0.1 W, 0603; Manufacturer: Yageo; Power_W: 100mW; TempCo: 200 ppm/C; Value_Code: 0000; Value: 0; EIA_Code: E24; SizeX_mm: 1.6; SizeZ_mm: 1; Value2: 0.1W; SizeArea_mm2: 1.28; AEC Qualified: N; VDC_V: 75V; AEC Category: Q200; SizeY_mm: 0.8; SizeAreaWB_mm2: 4.68
R46 = CMP-0022786-4: RES, 133 k, 1%, 0.1 W, 0603; Manufacturer: Yageo; Power_W: 100mW; TempCo: 100 ppm/C; Value: 133k; EIA_Code: E96; SizeX_mm: 1.6; SizeY_mm: 0.8; SizeZ_mm: 1; Value2: 0.1W; SizeArea_mm2: 1.28; AEC Qualified: N; VDC_V: 75V; AEC Category: Q200; SizeAreaWB_mm2: 4.68
R48 = CMP-0022914-5: RES, 21.0 k, 1%, 0.1 W, 0603; Manufacturer: Yageo; Power_W: 100mW; TempCo: 100 ppm/C; Value_Code: 21k0; Value: 21.0k; EIA_Code: E96; Res_ohm: 21k; SizeX_mm: 1.6; SizeY_mm: 0.8; SizeZ_mm: 1; Value2: 0.1W; SizeArea_mm2: 1.28; AEC Qualified: N; VDC_V: 75V; AEC Category: Q200; SizeAreaWB_mm2: 4.68
RT1 = CMP-0123150-1: Ceramic PTC Thermistor; Manufacturer: Thinking Electronic; SizeZ_mm: 21.5mm; Value: 50Ω; AEC Qualified: No; Tolerance_%: 30%; VDC_V: 270V
RV1 = CMP-0001785-2: VARISTOR 558V 4.5KA, TH; PartNumber: 820543011; Manufacturer: WURTH
S1 = CMP-0122038-1: Toggle Sw, SPDT, 1A, 30VDC, Panel/th Rohs Compliant: Yes; Manufacturer: Wurth Electronics; SizeZ_mm: 29.15mm; VDC_V: 30V; AEC Qualified: No; Coil Resistance_ohm: 30mΩ; Electromechanical Life: 50000Cycles
TP1-TP5 TP7-TP9 = 5000: Test Point, Miniature, Red, TH; Manufacturer: Keystone; CompType: Test Point Loop; U/M: EA
TP6 = 5001: Test Point, Miniature, Black, TH; Manufacturer: Keystone; CompType: Test Point Loop; U/M: EA
TP10-TP12 = CMP-0055138-2: Test Point, Miniature, Black, TH; Manufacturer: Keystone Electronics; ContactFinish: Silver; CNHeader: FALSE; Green_Lifecycle: Active; Green_REACh: Passed; CT: TRUE
U1 = UCC28180D: 8-PIN CONTINUOUS CONDUCTION MODE (CCM) PFC CONTROLLER, D0008A; Alternate Manufacturer: None; Manufacturer: Texas Instruments; SymbolCreator: a0411947; CompType: IC; U/M: EA
U2 = CMP-0073916-1: Dual, 5A, High-Speed Low-Side Power MOSFET Driver, D0008A (SOIC-8); Alternate Manufacturer: Texas Instruments; SizeAreaWB_mm2: 56.58; U/M: EA; SizeZ_mm: 1.75; SizeX_mm: 4.9; SizeY_mm: 6.2; SizeArea_mm2: 30.38; CompType: IC
U3 = CMP-0074092-1: 700-V Lowest Quiescent Current Off-Line Switcher, D0007A (SOIC-7); Alternate Manufacturer: Texas Instruments; SizeAreaWB_mm2: 55.2; U/M: EA; SizeZ_mm: 1.75; SizeX_mm: 6.0; SizeY_mm: 4.9; SizeArea_mm2: 29.4; CompType: IC

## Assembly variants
001: not fitted C21 FID1 FID2 FID3 R28 R44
